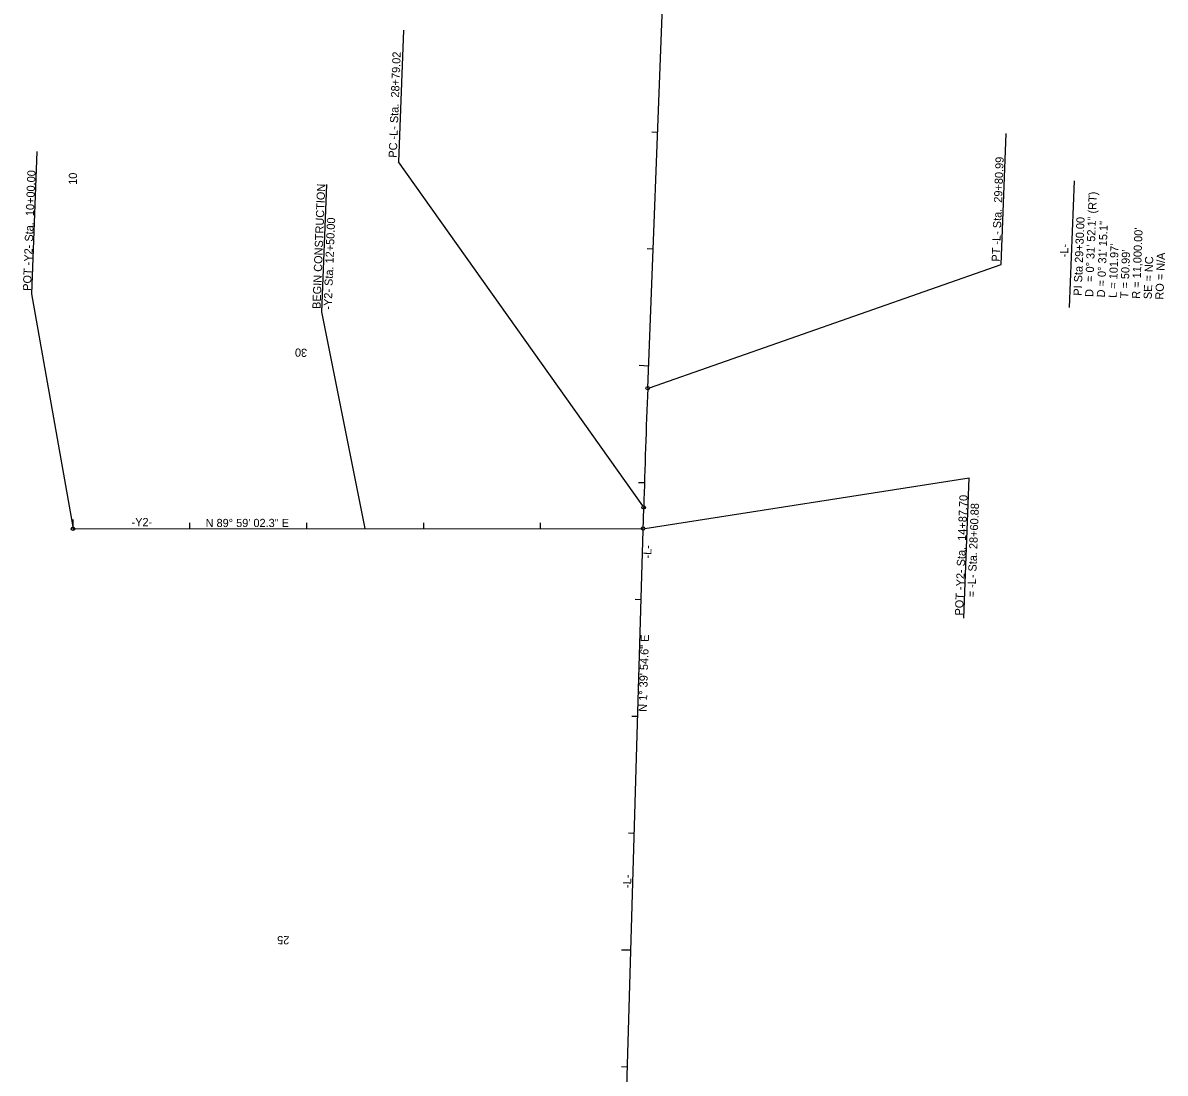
# Model space of a CAD drawing. Extents: x 2096901 to 2098386, y 684661 to 689731.
# Drawn here: x 2097192 to 2098169, y 686414 to 687312 of the extents above; entities that cross this region are included whole.
import ezdxf

# ---------------------------------------------------------------- set-up
doc = ezdxf.new("R2010")
doc.units = 0
for name, color, linetype in [('Prop Horizontal Alignment', 7, 'Continuous'), ('Prop Horizontal Alignment Curve and Spiral Data', 7, 'Continuous'), ('Prop Horizontal Alignment Direction Label', 7, 'Continuous'), ('Prop Horizontal Alignment Station Label', 7, 'Continuous'), ('Prop Horizontal Alignment Tick Label', 7, 'Continuous'), ('Prop Horizontal Alignment Tick Large', 7, 'Continuous'), ('Prop Horizontal Alignment Tick Small', 7, 'Continuous'), ('Scratch_Level_3', 7, 'Continuous'), ('Scratch_Level_5', 7, 'Continuous')]:
    doc.layers.add(name, color=color, linetype=linetype)

msp = doc.modelspace()

# ---------------------------------------------------------------- linework, layer by layer
at = {"layer": 'Prop Horizontal Alignment'}
for p, q in [((2097726.62, 686999.7), (2097785.25, 688528.39)), ((2097700.41, 686114.22), (2097723.19, 686897.79)), ((2097234.96, 686879.52), (2097722.66, 686879.66))]:
    msp.add_line(p, q, dxfattribs=at)
msp.add_arc((2108718.54, 686578.14), 11000, 177.803699, 178.33483, dxfattribs=at)
at = {"layer": 'Prop Horizontal Alignment Curve and Spiral Data'}
msp.add_line((2098087.49, 687068.67), (2098091.65, 687177.01), dxfattribs=at)
at = {"layer": 'Prop Horizontal Alignment Station Label'}
for p, q in [((2097517.71, 687306), (2097513.39, 687193.33)), ((2098028.96, 687105.52), (2098033.26, 687217.63)), ((2097199.7, 687080.42), (2097204.37, 687202.17)), ((2097722.34, 686899.03), (2097513.39, 687193.33)), ((2097447.9, 687064.97), (2097452.08, 687174.03)), ((2097728.05, 687000.16), (2098028.96, 687105.52)), ((2097234.96, 686881.02), (2097199.7, 687080.42)), ((2097484.96, 686879.59), (2097447.9, 687064.97)), ((2097724.16, 686879.66), (2098001.74, 686923.13)), ((2097997.13, 686802.98), (2098001.74, 686923.13))]:
    msp.add_line(p, q, dxfattribs=at)
for centre in [(2097726.62, 686999.7), (2097723.19, 686897.79), (2097234.96, 686879.52), (2097722.66, 686879.66)]:
    msp.add_circle(centre, 1.5, dxfattribs=at)
at = {"layer": 'Prop Horizontal Alignment Tick Large'}
for p, q in [((2097727.35, 687018.7), (2097719.36, 687019)), ((2097234.96, 686879.52), (2097234.96, 686887.52)), ((2097712.17, 686518.93), (2097704.18, 686519.16))]:
    msp.add_line(p, q, dxfattribs=at)
at = {"layer": 'Prop Horizontal Alignment Tick Small'}
for p, q in [((2097735.01, 687218.55), (2097730.02, 687218.74)), ((2097731.18, 687118.62), (2097726.19, 687118.81)), ((2097723.82, 686918.76), (2097718.82, 686918.91)), ((2097334.96, 686879.55), (2097334.96, 686884.55)), ((2097434.96, 686879.58), (2097434.96, 686884.58)), ((2097534.96, 686879.61), (2097534.96, 686884.61)), ((2097634.96, 686879.63), (2097634.96, 686884.63)), ((2097720.89, 686818.8), (2097715.89, 686818.95)), ((2097717.98, 686718.84), (2097712.99, 686718.99)), ((2097715.08, 686618.89), (2097710.08, 686619.03)), ((2097709.27, 686418.97), (2097704.27, 686419.12))]:
    msp.add_line(p, q, dxfattribs=at)
at = {"layer": 'Scratch_Level_3'}
for p, q in [((2097726.62, 686999.7), (2097785.25, 688528.39)), ((2097700.41, 686114.22), (2097723.19, 686897.79)), ((2097234.96, 686879.52), (2097722.66, 686879.66))]:
    msp.add_line(p, q, dxfattribs=at)
at = {"layer": 'Scratch_Level_5'}
msp.add_arc((2108718.54, 686578.14), 11000, 177.803699, 178.33483, dxfattribs=at)

# ---------------------------------------------------------------- texts
at = {"layer": 'Prop Horizontal Alignment Curve and Spiral Data'}
for s, p in [('= 0%%d 31\' 52.1" (RT)', (2098108.01, 687090.51)), ('PI Sta 29+30.00', (2098097.84, 687078.71)), ('D = 0%%d 31\' 15.1"', (2098117.8, 687077.27)), ("R = 11,000.00'", (2098147.78, 687076.12)), ('-L-', (2098086.22, 687111.6)), ("L = 101.97'", (2098127.79, 687076.89)), ("T = 50.99'", (2098137.79, 687076.51)), ('RO = N/A', (2098167.76, 687075.36)), ('SE = NC', (2098157.77, 687075.74)), ('D', (2098107.81, 687077.66))]:
    msp.add_text(s, height=7, rotation=87.8037, dxfattribs=at).set_placement(p)
at = {"layer": 'Prop Horizontal Alignment Direction Label'}
for s, rotation, p in [('N 89%%d 59\' 02.3" E', 0.01603, (2097348.41, 686880.94)), ('N 1%%d 39\' 54.6" E', 88.33483, (2097725.79, 686722.81))]:
    msp.add_text(s, height=7, rotation=rotation, dxfattribs=at).set_placement(p)
at = {"layer": 'Prop Horizontal Alignment Station Label'}
for s, rotation, p in [('PC -L- Sta.  28+79.02', 87.8037, (2097511.89, 687196.75)), ('PT -L- Sta.  29+80.99', 87.8037, (2098027.81, 687107.86)), ('POT -Y2- Sta.  10+00.00', 87.8037, (2097199.01, 687082.87)), ('BEGIN CONSTRUCTION', 87.8037, (2097446.69, 687067.44)), ('-Y2- Sta. 12+50.00', 87.8037, (2097456.26, 687066.81)), ('POT -Y2- Sta.  14+87.70', 87.8037, (2097996.37, 686805.14)), ('= -L- Sta. 28+60.88', 87.8037, (2098006.98, 686820.67)), ('-Y2-', 0.01603, (2097285.04, 686881.68)), ('-L-', 88.33483, (2097729.65, 686854.02)), ('-L-', 88.33483, (2097712.34, 686572.11))]:
    msp.add_text(s, height=7, rotation=rotation, dxfattribs=at).set_placement(p)
at = {"layer": 'Prop Horizontal Alignment Tick Label'}
for s, rotation, p in [('10', 90.01603, (2097238.38, 687173.67)), ('30', 177.8037, (2097435.38, 687033.4)), ('25', 178.33483, (2097420.1, 686530.92))]:
    msp.add_text(s, height=7, rotation=rotation, dxfattribs=at).set_placement(p)

doc.saveas('drawing.dxf')
